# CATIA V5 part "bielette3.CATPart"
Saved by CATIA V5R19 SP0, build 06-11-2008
Part number: bielette3
Bounding box of the stored display mesh (mm): x -129.964 to 19.964, y 335.036 to 429.964, z -30 to 30
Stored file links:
  C:\Users\Thibaud\Desktop\IFMA\thinkmotion\IAO\modele_catia\bielette3.CATPart
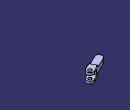
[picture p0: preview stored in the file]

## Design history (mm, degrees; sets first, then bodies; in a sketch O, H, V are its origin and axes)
Body1 (main body)
  Plane1: stored without definition
  Line1: stored without definition
  Line2: stored without definition
  Line3 "axe_pivot_bielette3_sabot2": stored without definition
  Sketch1 on Plane1, origin (0, 0, 0), H (1, 0, 0), V (0, 1, 0)
    line L1 (-38.4458, 413.1378) -> (-118.9443, 372.8885)
    arc A1 centre (-110, 355) radius 20 from (-118.9443, 372.8885) to (-101.0557, 337.1115) ccw
    point P3 (-110, 355)
    line L2 (-101.0557, 337.1115) -> (-20.5573, 377.3607)
    line L3 (-20.5573, 377.3607) -> (-38.4458, 413.1378)
    reference projected line E1 (0, 410) -> (-110, 355) from Line1
    reference projected point E2 (-110, 355) from Line3
    length L3 = 40
    distance P3 L3 = 90
    tangency: A1 L1, L2 A1
    perpendicularity: L3 L1
    parallelism: L2 L1, L1 E1
    coincidence: P3 E2
  Pad1: profile Sketch1, direction (0, 0, 1), length 15, mirrored extent
  Line4 "axe_pivot_bielette3_levier": stored without definition
  Sketch2 on end face of Pad1, origin (0, 0, 15), H (1, 0, 0), V (0, 1, 0)
    circle A1 centre (0, 410) radius 10
    point P1 (0, 410)
    reference projected point E1 (0, 410) from Line4
    arc A2 centre (0, 410) radius 20 from (8.9443, 392.1115) to (-8.9443, 427.8885) ccw
    point P2 (0, 410)
    line L1 (-35.7771, 369.7508) -> (8.9443, 392.1115)
    point P3 (-35.7771, 369.7508)
    line L2 (-8.9443, 427.8885) -> (-53.6656, 405.5279)
    point P4 (-53.6656, 405.5279)
    line L3 (-53.6656, 405.5279) -> (-35.7771, 369.7508)
    point P5 (-53.6656, 405.5279)
    point P6 (-35.7771, 369.7508)
    reference projected line E2 (-47.3901, 408.6656) -> (-118.9443, 372.8885) from edge [face of Pad1 from Sketch1.L1 | end face of Pad1]
    radius A1 = 10
    radius A2 = 20
    distance P2 L3 = 50
    coincidence: P1 E1, P5 L2, L3 P3, P4 P5, P3 P6
    concentricity: A2 A1
    tangency: L1 A2, L2 A2
    perpendicularity: L2 L3
    parallelism: L1 L2, L2 E2
  Pad2: profile Sketch2, direction (0, 0, 1), length 15
  RectPattern1: of Pad2, direction 1 instances 2, spacing 45, along edge [face of Pad2 | face of Pad1 from Sketch1.L3] reversed
  Fillet1: radius 5, on edge [end face of Pad1 | face of Pad2 from Sketch2.L3]; edge [face of Pad2 from Sketch2.L3 | end face of Pad2]; edge [face of RectPattern1 | face of RectPattern1]; edge [face of RectPattern1 | start face of Pad1]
